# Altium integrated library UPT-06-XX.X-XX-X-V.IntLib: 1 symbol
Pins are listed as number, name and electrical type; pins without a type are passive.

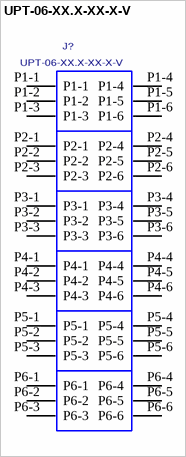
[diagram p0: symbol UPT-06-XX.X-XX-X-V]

## UPT-06-XX.X-XX-X-V
designator J?
UPT-V, ASSEMBLY.; MANUFACTURER: SAMTEC
footprint UPT-06-XX.X-XX-X-V
pins: P1-1, P1-2, P1-3, P1-4, P1-5, P1-6, P2-1, P2-2, P2-3, P2-4, P2-5, P2-6, P3-1, P3-2, P3-3, P3-4, P3-5, P3-6, P4-1, P4-2, P4-3, P4-4, P4-5, P4-6, P5-1, P5-2, P5-3, P5-4, P5-5, P5-6, P6-1, P6-2, P6-3, P6-4, P6-5, P6-6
